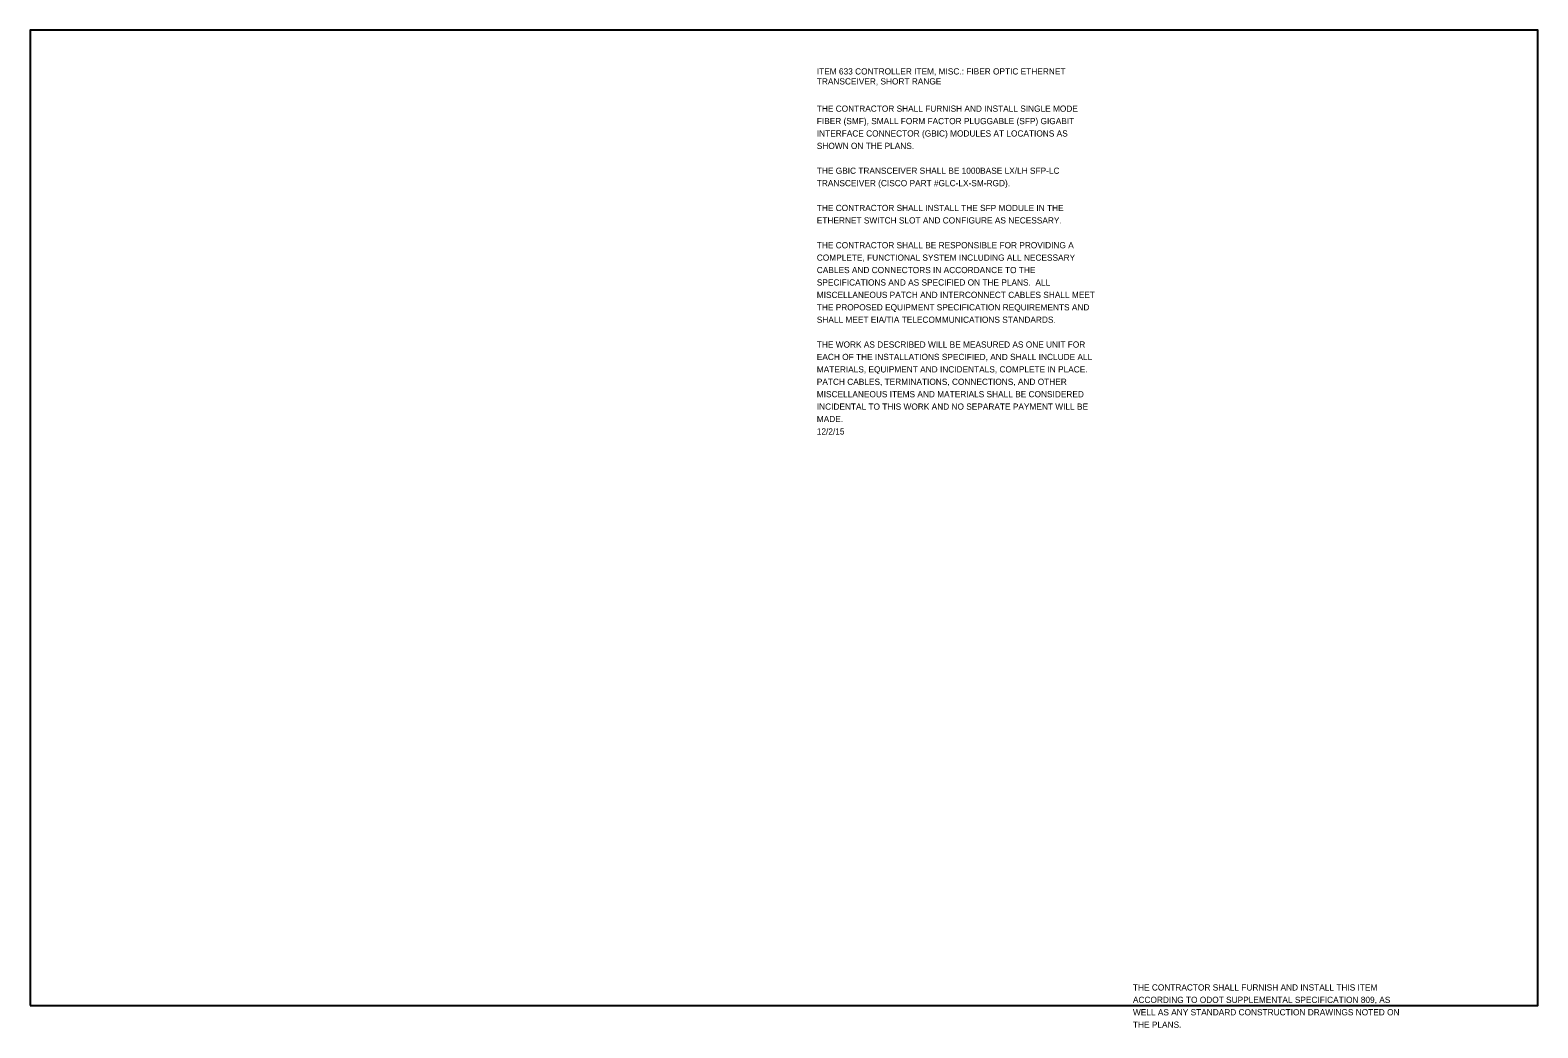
# Model space of a CAD drawing. Extents: x -36.9 to 49.6, y -47.1 to 37.
# Drawn here: x -36.94 to -2.94, y 14.48 to 36.98 of the extents above; entities that cross this region are included whole.
import ezdxf

# ---------------------------------------------------------------- set-up
doc = ezdxf.new("R2010")
doc.units = 0
for name, color, linetype in [('SH_Cut_Line', 7, 'Continuous'), ('SH_Data', 7, 'Continuous'), ('SH_Text', 7, 'Continuous')]:
    doc.layers.add(name, color=color, linetype=linetype)

msp = doc.modelspace()

# ---------------------------------------------------------------- linework, layer by layer
at = {"layer": 'SH_Cut_Line'}
msp.add_lwpolyline([(-36.938, 14.983), (-2.938, 14.983), (-2.938, 36.983), (-36.938, 36.983)], close=True, dxfattribs=at)

# ---------------------------------------------------------------- texts
at = {"layer": 'SH_Data'}
for s, p in [('ITEM 633 CONTROLLER ITEM, MISC.: FIBER OPTIC ETHERNET ', (-19.198, 35.983)), ('TRANSCEIVER, SHORT RANGE', (-19.198, 35.758))]:
    msp.add_text(s, height=0.14, dxfattribs=at).set_placement(p)
at = {"layer": 'SH_Text'}
for s, p in [('THE CONTRACTOR SHALL FURNISH AND INSTALL SINGLE MODE ', (-19.198, 35.143)), ('FIBER (SMF), SMALL FORM FACTOR PLUGGABLE (SFP) GIGABIT ', (-19.198, 34.863)), ('INTERFACE CONNECTOR (GBIC) MODULES AT LOCATIONS AS ', (-19.198, 34.583)), ('SHOWN ON THE PLANS. ', (-19.198, 34.303)), ('THE GBIC TRANSCEIVER SHALL BE 1000BASE LX/LH SFP-LC ', (-19.198, 33.743)), ('TRANSCEIVER (CISCO PART #GLC-LX-SM-RGD).  ', (-19.198, 33.463)), ('THE CONTRACTOR SHALL INSTALL THE SFP MODULE IN THE ', (-19.198, 32.903)), ('ETHERNET SWITCH SLOT AND CONFIGURE AS NECESSARY.', (-19.198, 32.623)), ('THE CONTRACTOR SHALL BE RESPONSIBLE FOR PROVIDING A ', (-19.198, 32.063)), ('COMPLETE, FUNCTIONAL SYSTEM INCLUDING ALL NECESSARY ', (-19.198, 31.783)), ('CABLES AND CONNECTORS IN ACCORDANCE TO THE ', (-19.198, 31.503)), ('SPECIFICATIONS AND AS SPECIFIED ON THE PLANS.  ALL ', (-19.198, 31.223)), ('MISCELLANEOUS PATCH AND INTERCONNECT CABLES SHALL MEET ', (-19.198, 30.943)), ('THE PROPOSED EQUIPMENT SPECIFICATION REQUIREMENTS AND ', (-19.198, 30.663)), ('SHALL MEET EIA/TIA TELECOMMUNICATIONS STANDARDS.', (-19.198, 30.383)), ('THE WORK AS DESCRIBED WILL BE MEASURED AS ONE UNIT FOR ', (-19.198, 29.823)), ('EACH OF THE INSTALLATIONS SPECIFIED, AND SHALL INCLUDE ALL ', (-19.198, 29.543)), ('MATERIALS, EQUIPMENT AND INCIDENTALS, COMPLETE IN PLACE. ', (-19.198, 29.263)), ('PATCH CABLES, TERMINATIONS, CONNECTIONS, AND OTHER ', (-19.198, 28.983)), ('MISCELLANEOUS ITEMS AND MATERIALS SHALL BE CONSIDERED ', (-19.198, 28.703)), ('INCIDENTAL TO THIS WORK AND NO SEPARATE PAYMENT WILL BE ', (-19.198, 28.423)), ('MADE.', (-19.198, 28.143)), ('12/2/15', (-19.198, 27.863)), ('THE CONTRACTOR SHALL FURNISH AND INSTALL THIS ITEM ', (-12.069, 15.324)), ('ACCORDING TO ODOT SUPPLEMENTAL SPECIFICATION 809, AS ', (-12.069, 15.044)), ('WELL AS ANY STANDARD CONSTRUCTION DRAWINGS NOTED ON ', (-12.069, 14.764)), ('THE PLANS.', (-12.069, 14.484))]:
    msp.add_text(s, height=0.14, dxfattribs=at).set_placement(p)

doc.saveas('drawing.dxf')
